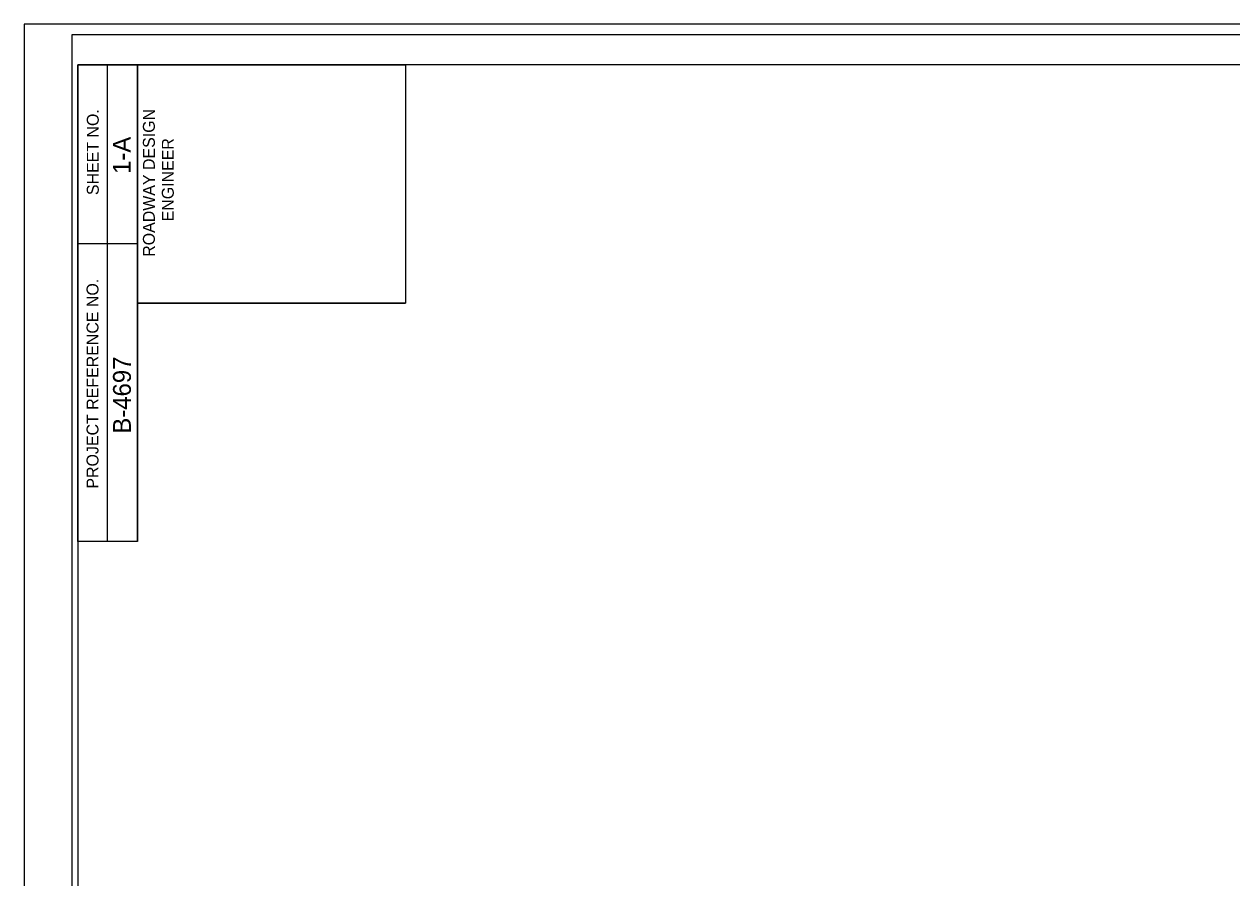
# Model space of a CAD drawing. Extents: x 2026893 to 2039781, y 729195 to 739590.
# Drawn here: x 2031243 to 2033017, y 738335 to 739588 of the extents above; entities that cross this region are included whole.
import ezdxf

# ---------------------------------------------------------------- set-up
doc = ezdxf.new("R2010")
doc.units = 0
for name, color, linetype in [('Sheet Cutting Line CELL', 7, 'Continuous'), ('Sheet Data Field CELL', 7, 'Continuous'), ('Sheet Plan CELL', 7, 'Continuous'), ('Sheet Plot Border Inside CELL', 7, 'Continuous'), ('Sheet Plot Border Outside CELL', 7, 'Continuous')]:
    doc.layers.add(name, color=color, linetype=linetype)

msp = doc.modelspace()

# ---------------------------------------------------------------- linework, layer by layer
at = {"layer": 'Sheet Cutting Line CELL'}
msp.add_line((2031242.8, 739588.2), (2031242.8, 733695.9), dxfattribs=at)
at = {"layer": 'Sheet Plan CELL'}
for p, q in [((2031365.5, 738828.5), (2031365.5, 739528.7)), ((2031409.2, 738828.5), (2031409.2, 739528.7)), ((2031409.2, 738828.5), (2031409.2, 739528.7)), ((2031321.7, 739266.2), (2031409.2, 739266.2)), ((2031409.2, 739178.7), (2031802.8, 739178.7))]:
    msp.add_line(p, q, dxfattribs=at)
for points in [[(2031321.6, 739528.7), (2031321.6, 734278.7), (2034996.6, 734278.7), (2034996.6, 739528.7)], [(2031321.6, 738828.5), (2031321.6, 739528.7), (2031409.2, 739528.7), (2031409.2, 738828.5)], [(2031409.2, 739178.7), (2031409.2, 739528.7), (2031803, 739528.7), (2031803, 739178.7)]]:
    msp.add_lwpolyline(points, close=True, dxfattribs=at)
at = {"layer": 'Sheet Plot Border Inside CELL'}
msp.add_lwpolyline([(2035005.3, 733741.4), (2035005.3, 739572.4), (2031312.8, 739572.4), (2031312.8, 733741.4)], close=True, dxfattribs=at)
at = {"layer": 'Sheet Plot Border Outside CELL'}
msp.add_lwpolyline([(2035075.3, 733695.9), (2035075.3, 739588.2), (2031242.8, 739588.2), (2031242.8, 733695.9)], close=True, dxfattribs=at)

# ---------------------------------------------------------------- texts
at = {"layer": 'Sheet Data Field CELL'}
for s, p in [('1-A', (2031399.4, 739368.3)), ('B-4697', (2031399.6, 738986.9))]:
    msp.add_text(s, height=26.25, rotation=90, dxfattribs=at).set_placement(p)
at = {"layer": 'Sheet Plan CELL'}
for s, p in [('SHEET NO.', (2031352.4, 739337.2)), ('ROADWAY DESIGN', (2031434.8, 739246.6)), ('ENGINEER', (2031462.6, 739298.6)), ('PROJECT REFERENCE NO.', (2031352, 738906.2))]:
    msp.add_text(s, height=17.5, rotation=90, dxfattribs=at).set_placement(p)

doc.saveas('drawing.dxf')
